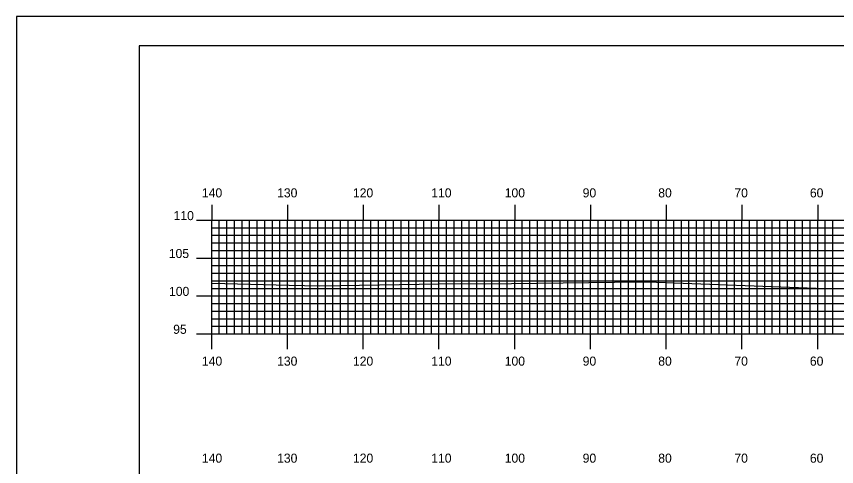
# Model space of a CAD drawing. Extents: x 1778712 to 1779055, y 442591 to 442811.
# Drawn here: x 1778712 to 1778820.3, y 442751.2 to 442810.5 of the extents above; entities that cross this region are included whole.
import ezdxf

# ---------------------------------------------------------------- set-up
doc = ezdxf.new("R2010")
doc.units = 0
for name, color, linetype in [('BORDER', 7, 'Continuous'), ('H_V ANNOTATION', 7, 'Continuous'), ('MAJOR', 7, 'Continuous'), ('MINOR', 7, 'Continuous'), ('PLOT BOUNDARY', 7, 'Continuous'), ('S_Roadway_Centerline', 7, 'Continuous')]:
    doc.layers.add(name, color=color, linetype=linetype)

msp = doc.modelspace()

# ---------------------------------------------------------------- linework, layer by layer
at = {"layer": 'BORDER'}
msp.add_lwpolyline([(1778728.22, 442596.67), (1779048.22, 442596.67), (1779048.22, 442806.67), (1778728.22, 442806.67)], close=True, dxfattribs=at)
at = {"layer": 'MAJOR'}
for p, q in [((1778737.82, 442785.67), (1778737.82, 442783.67)), ((1778747.82, 442785.67), (1778747.82, 442783.67)), ((1778757.82, 442785.67), (1778757.82, 442783.67)), ((1778767.82, 442785.67), (1778767.82, 442783.67)), ((1778777.82, 442785.67), (1778777.82, 442783.67)), ((1778787.82, 442785.67), (1778787.82, 442783.67)), ((1778797.82, 442785.67), (1778797.82, 442783.67)), ((1778807.82, 442785.67), (1778807.82, 442783.67)), ((1778817.82, 442785.67), (1778817.82, 442783.67)), ((1778735.81, 442783.67), (1778737.82, 442783.67)), ((1778737.82, 442783.67), (1779017.82, 442783.67)), ((1778737.82, 442768.67), (1778737.82, 442783.67)), ((1778737.82, 442768.67), (1778737.82, 442783.67)), ((1778737.82, 442783.67), (1779017.82, 442783.67)), ((1778747.82, 442768.67), (1778747.82, 442783.67)), ((1778757.82, 442768.67), (1778757.82, 442783.67)), ((1778767.82, 442768.67), (1778767.82, 442783.67)), ((1778777.82, 442768.67), (1778777.82, 442783.67)), ((1778787.82, 442768.67), (1778787.82, 442783.67)), ((1778797.82, 442768.67), (1778797.82, 442783.67)), ((1778807.82, 442768.67), (1778807.82, 442783.67)), ((1778817.82, 442768.67), (1778817.82, 442783.67)), ((1778735.81, 442778.67), (1778737.82, 442778.67)), ((1778737.82, 442778.67), (1779017.82, 442778.67)), ((1778735.81, 442773.67), (1778737.82, 442773.67)), ((1778737.82, 442773.67), (1779017.82, 442773.67)), ((1778735.81, 442768.67), (1778737.82, 442768.67)), ((1778737.82, 442768.67), (1779017.82, 442768.67)), ((1778737.82, 442768.67), (1779017.82, 442768.67)), ((1778737.82, 442766.66), (1778737.82, 442768.67)), ((1778747.82, 442766.66), (1778747.82, 442768.67)), ((1778757.82, 442766.66), (1778757.82, 442768.67)), ((1778767.82, 442766.66), (1778767.82, 442768.67)), ((1778777.82, 442766.66), (1778777.82, 442768.67)), ((1778787.82, 442766.66), (1778787.82, 442768.67)), ((1778797.82, 442766.66), (1778797.82, 442768.67)), ((1778807.82, 442766.66), (1778807.82, 442768.67)), ((1778817.82, 442766.66), (1778817.82, 442768.67))]:
    msp.add_line(p, q, dxfattribs=at)
at = {"layer": 'MINOR'}
for p, q in [((1778738.82, 442768.67), (1778738.82, 442783.67)), ((1778739.82, 442768.67), (1778739.82, 442783.67)), ((1778740.82, 442768.67), (1778740.82, 442783.67)), ((1778741.82, 442768.67), (1778741.82, 442783.67)), ((1778742.82, 442768.67), (1778742.82, 442783.67)), ((1778743.82, 442768.67), (1778743.82, 442783.67)), ((1778744.82, 442768.67), (1778744.82, 442783.67)), ((1778745.82, 442768.67), (1778745.82, 442783.67)), ((1778746.82, 442768.67), (1778746.82, 442783.67)), ((1778748.82, 442768.67), (1778748.82, 442783.67)), ((1778749.82, 442768.67), (1778749.82, 442783.67)), ((1778750.82, 442768.67), (1778750.82, 442783.67)), ((1778751.82, 442768.67), (1778751.82, 442783.67)), ((1778752.82, 442768.67), (1778752.82, 442783.67)), ((1778753.82, 442768.67), (1778753.82, 442783.67)), ((1778754.82, 442768.67), (1778754.82, 442783.67)), ((1778755.82, 442768.67), (1778755.82, 442783.67)), ((1778756.82, 442768.67), (1778756.82, 442783.67)), ((1778758.82, 442768.67), (1778758.82, 442783.67)), ((1778759.82, 442768.67), (1778759.82, 442783.67)), ((1778760.82, 442768.67), (1778760.82, 442783.67)), ((1778761.82, 442768.67), (1778761.82, 442783.67)), ((1778762.82, 442768.67), (1778762.82, 442783.67)), ((1778763.82, 442768.67), (1778763.82, 442783.67)), ((1778764.82, 442768.67), (1778764.82, 442783.67)), ((1778765.82, 442768.67), (1778765.82, 442783.67)), ((1778766.82, 442768.67), (1778766.82, 442783.67)), ((1778768.82, 442768.67), (1778768.82, 442783.67)), ((1778769.82, 442768.67), (1778769.82, 442783.67)), ((1778770.82, 442768.67), (1778770.82, 442783.67)), ((1778771.82, 442768.67), (1778771.82, 442783.67)), ((1778772.82, 442768.67), (1778772.82, 442783.67)), ((1778773.82, 442768.67), (1778773.82, 442783.67)), ((1778774.82, 442768.67), (1778774.82, 442783.67)), ((1778775.82, 442768.67), (1778775.82, 442783.67)), ((1778776.82, 442768.67), (1778776.82, 442783.67)), ((1778778.82, 442768.67), (1778778.82, 442783.67)), ((1778779.82, 442768.67), (1778779.82, 442783.67)), ((1778780.82, 442768.67), (1778780.82, 442783.67)), ((1778781.82, 442768.67), (1778781.82, 442783.67)), ((1778782.82, 442768.67), (1778782.82, 442783.67)), ((1778783.82, 442768.67), (1778783.82, 442783.67)), ((1778784.82, 442768.67), (1778784.82, 442783.67)), ((1778785.82, 442768.67), (1778785.82, 442783.67)), ((1778786.82, 442768.67), (1778786.82, 442783.67)), ((1778788.82, 442768.67), (1778788.82, 442783.67)), ((1778789.82, 442768.67), (1778789.82, 442783.67)), ((1778790.82, 442768.67), (1778790.82, 442783.67)), ((1778791.82, 442768.67), (1778791.82, 442783.67)), ((1778792.82, 442768.67), (1778792.82, 442783.67)), ((1778793.82, 442768.67), (1778793.82, 442783.67)), ((1778794.82, 442768.67), (1778794.82, 442783.67)), ((1778795.82, 442768.67), (1778795.82, 442783.67)), ((1778796.82, 442768.67), (1778796.82, 442783.67)), ((1778798.82, 442768.67), (1778798.82, 442783.67)), ((1778799.82, 442768.67), (1778799.82, 442783.67)), ((1778800.82, 442768.67), (1778800.82, 442783.67)), ((1778801.82, 442768.67), (1778801.82, 442783.67)), ((1778802.82, 442768.67), (1778802.82, 442783.67)), ((1778803.82, 442768.67), (1778803.82, 442783.67)), ((1778804.82, 442768.67), (1778804.82, 442783.67)), ((1778805.82, 442768.67), (1778805.82, 442783.67)), ((1778806.82, 442768.67), (1778806.82, 442783.67)), ((1778808.82, 442768.67), (1778808.82, 442783.67)), ((1778809.82, 442768.67), (1778809.82, 442783.67)), ((1778810.82, 442768.67), (1778810.82, 442783.67)), ((1778811.82, 442768.67), (1778811.82, 442783.67)), ((1778812.82, 442768.67), (1778812.82, 442783.67)), ((1778813.82, 442768.67), (1778813.82, 442783.67)), ((1778814.82, 442768.67), (1778814.82, 442783.67)), ((1778815.82, 442768.67), (1778815.82, 442783.67)), ((1778816.82, 442768.67), (1778816.82, 442783.67)), ((1778818.82, 442768.67), (1778818.82, 442783.67)), ((1778819.82, 442768.67), (1778819.82, 442783.67)), ((1778737.82, 442782.67), (1779017.82, 442782.67)), ((1778737.82, 442782.67), (1778739.82, 442782.67)), ((1778737.82, 442781.67), (1779017.82, 442781.67)), ((1778737.82, 442781.67), (1778739.82, 442781.67)), ((1778737.82, 442780.67), (1779017.82, 442780.67)), ((1778737.82, 442780.67), (1778739.82, 442780.67)), ((1778737.82, 442779.67), (1779017.82, 442779.67)), ((1778737.82, 442779.67), (1778739.82, 442779.67)), ((1778737.82, 442777.67), (1779017.82, 442777.67)), ((1778737.82, 442777.67), (1778739.82, 442777.67)), ((1778737.82, 442776.67), (1779017.82, 442776.67)), ((1778737.82, 442776.67), (1778739.82, 442776.67)), ((1778737.82, 442775.67), (1779017.82, 442775.67)), ((1778737.82, 442775.67), (1778739.82, 442775.67)), ((1778737.82, 442774.67), (1779017.82, 442774.67)), ((1778737.82, 442774.67), (1778739.82, 442774.67)), ((1778737.82, 442772.67), (1779017.82, 442772.67)), ((1778737.82, 442772.67), (1778739.82, 442772.67)), ((1778737.82, 442771.67), (1779017.82, 442771.67)), ((1778737.82, 442771.67), (1778739.82, 442771.67)), ((1778737.82, 442770.67), (1779017.82, 442770.67)), ((1778737.82, 442770.67), (1778739.82, 442770.67)), ((1778737.82, 442769.67), (1779017.82, 442769.67)), ((1778737.82, 442769.67), (1778739.82, 442769.67))]:
    msp.add_line(p, q, dxfattribs=at)
at = {"layer": 'PLOT BOUNDARY'}
msp.add_lwpolyline([(1778712.03, 442590.55), (1779052.03, 442590.55), (1779052.03, 442810.55), (1778712.03, 442810.55)], close=True, dxfattribs=at)
at = {"layer": 'S_Roadway_Centerline'}
msp.add_lwpolyline([(1778737.82, 442775.37), (1778748.04, 442775.09), (1778752.11, 442774.99), (1778767.84, 442775.25), (1778770.67, 442775.32), (1778774.01, 442775.25), (1778790.99, 442775.48), (1778793.76, 442775.53), (1778796.52, 442775.48), (1778817.64, 442774.69), (1778820.42, 442774.66)], dxfattribs=at)

# ---------------------------------------------------------------- texts
at = {"layer": 'H_V ANNOTATION'}
for s, p in [('140', (1778736.52, 442786.67)), ('130', (1778746.45, 442786.67)), ('120', (1778756.46, 442786.67)), ('110', (1778766.8, 442786.67)), ('100', (1778776.5, 442786.67)), ('90', (1778786.79, 442786.67)), ('80', (1778796.77, 442786.67)), ('70', (1778806.82, 442786.67)), ('60', (1778816.79, 442786.67)), ('110', (1778732.78, 442783.67)), ('105', (1778732.15, 442778.67)), ('100', (1778732.18, 442773.67)), ('95', (1778732.73, 442768.67)), ('140', (1778736.52, 442764.47)), ('130', (1778746.45, 442764.47)), ('120', (1778756.46, 442764.47)), ('110', (1778766.8, 442764.47)), ('100', (1778776.5, 442764.47)), ('90', (1778786.79, 442764.47)), ('80', (1778796.77, 442764.47)), ('70', (1778806.82, 442764.47)), ('60', (1778816.79, 442764.47)), ('140', (1778736.52, 442751.67)), ('130', (1778746.45, 442751.67)), ('120', (1778756.46, 442751.67)), ('110', (1778766.8, 442751.67)), ('100', (1778776.5, 442751.67)), ('90', (1778786.79, 442751.67)), ('80', (1778796.77, 442751.67)), ('70', (1778806.82, 442751.67)), ('60', (1778816.79, 442751.67))]:
    msp.add_text(s, height=1.2, dxfattribs=at).set_placement(p)
at = {"layer": 'MAJOR'}
msp.add_text('-', height=0.012, dxfattribs=at).set_placement((1778737.81, 442768.67))

doc.saveas('drawing.dxf')
